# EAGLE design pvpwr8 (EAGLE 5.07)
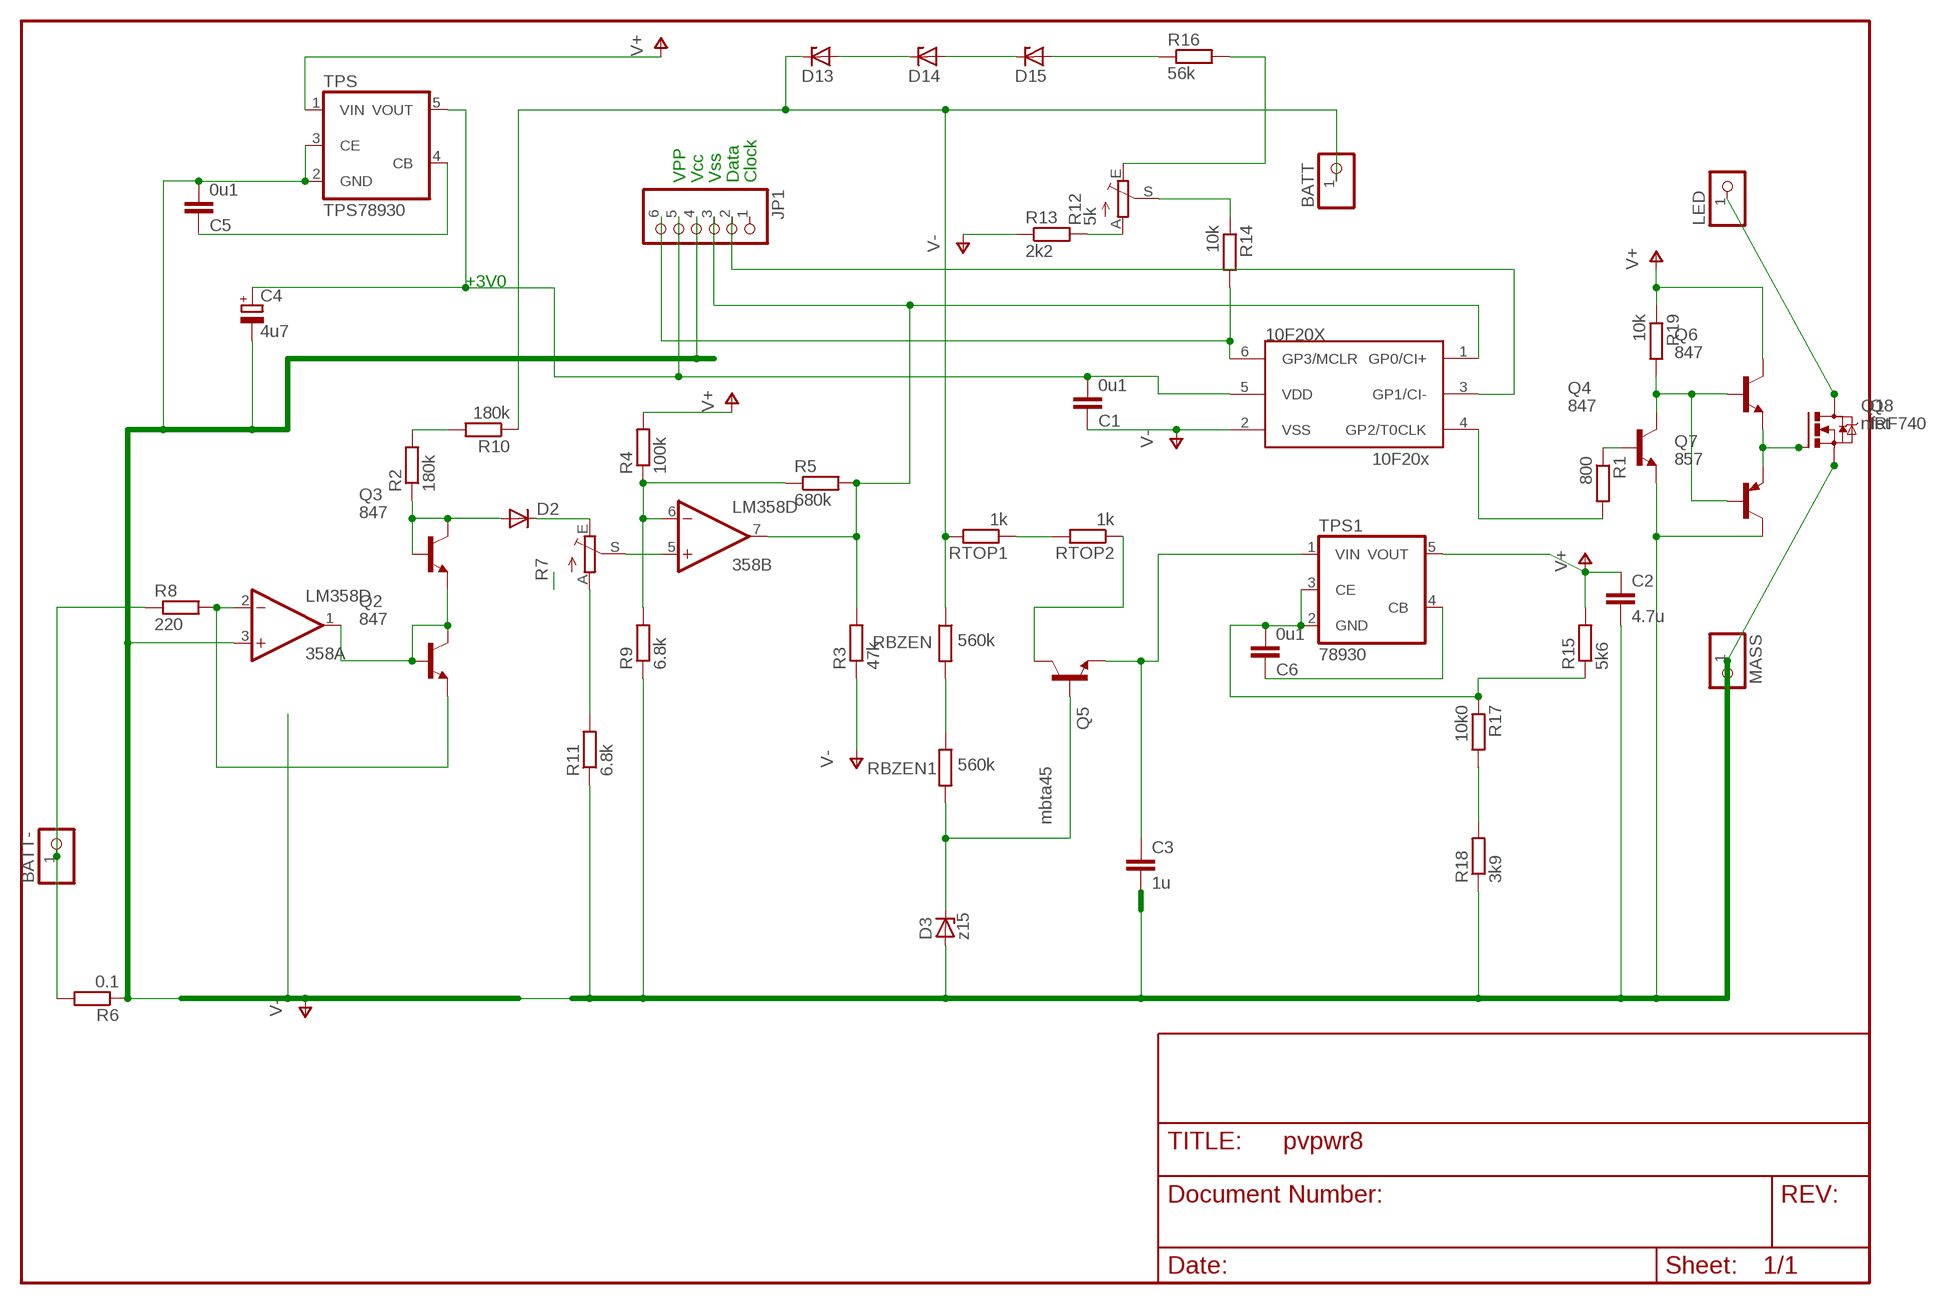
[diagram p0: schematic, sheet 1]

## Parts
10F20X  10F20x  PIC10F204OT  [SOT23-6]
358  LM358D  [SO08]
BATT  PINHD-1X1  [1X01]
BATT-  PINHD-1X1  [1X01]
C1  0u1  C-EUC1206  [C1206]
C2  4.7u  C-EUC1206  [C1206]
C3  1u  C-EUC1206  [C1206]
C4  4u7  CPOL-EUSMCA  [SMC_A]
C5  0u1  C-EUC0805  [C0805]
C6  0u1  C-EUC0805  [C0805]
D2  DIODE-SOD80C  [SOD80C]
D3  z15  ZENER-DIODESOD80C  [SOD80C]
D13  ZENER-DIODESOD80C  [SOD80C]
D14  ZENER-DIODESOD80C  [SOD80C]
D15  ZENER-DIODESOD80C  [SOD80C]
JP1  PINHD-1X6  [1X06BOX]
LED  PINHD-1X1  [1X01]
MASS  PINHD-1X1  [1X01]
Q1  nfet  N-HEXFET_DPAK-  [TO252]
Q2  847  BC847ALT1SMD  [SOT23]
Q3  847  BC847ALT1SMD  [SOT23]
Q4  847  BC847ALT1SMD  [SOT23]
Q5  mbta45  BC847ALT1SMD  [SOT23]
Q6  847  BC847ALT1SMD  [SOT23]
Q7  857  BC857ALT1SMD  [SOT23-BEC]
Q8  IRF740  [TO220BV]
R1  800  R-EU_R0805  [R0805]
R2  180k  R-EU_R1206  [R1206]
R3  47k  R-EU_R0805  [R0805]
R4  100k  R-EU_R0805  [R0805]
R5  680k  R-EU_R1206  [R1206]
R6  0.1  R-EU_R2512  [R2512]
R7  TRIM_EU-S64W  [S64W]
R8  220  R-EU_R0805  [R0805]
R9  6.8k  R-EU_R0805  [R0805]
R10  180k  R-EU_R1206  [R1206]
R11  6.8k  R-EU_R0805  [R0805]
R12  5k  TRIM_EU-S64W  [S64W]
R13  2k2  R-EU_R0805  [R0805]
R14  10k  R-EU_R0805  [R0805]
R15  5k6  R-EU_R0805  [R0805]
R16  56k  R-EU_R0805  [R0805]
R17  10k0  R-EU_R0805  [R0805]
R18  3k9  R-EU_R0805  [R0805]
R19  10k  R-EU_R0805  [R0805]
RBZEN  560k  R-EU_R1206  [R1206]
RBZEN1  560k  R-EU_R1206  [R1206]
RTOP1  1k  R-EU_R1206  [R1206]
RTOP2  1k  R-EU_R1206  [R1206]
TPS  TPS78930  TPS78930SOT23-5  [SOT25]
TPS1  78930  TPS78930SOT23-5  [SOT25]

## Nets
CB: D3.C Q5.1(B) RBZEN1.2
GND1: C6.1 TPS1.4(CB)
HOT: LED.1 Q1.3(D) Q8.D
N$1: Q4.1(B) R1.1
N$2: R7.A R11.2
N$3: BATT-.1 R6.2 R8.1
N$4: 10F20X.1(GP0/CI+) 358.7(B:OUT) JP1.3 R3.2 R5.2
N$5: 10F20X.4(GP2/T0CLK) R1.2
N$6: R2.2 R10.2
N$7: 358.1(A:OUT) Q2.1(B) Q2.3(C) Q3.2(E)
N$8: 10F20X.3(GP1/CI-) JP1.2
N$9: 10F20X.5(VDD) C1.2 C4.+ JP1.5 TPS.5(VOUT)
N$10: 358.2(A:-IN) Q2.2(E) R8.2
N$11: C5.1 TPS.4(CB)
N$12: D2.A Q3.1(B) Q3.3(C) R2.1
N$13: D2.C R7.E
N$15: 358.5(B:+IN) R7.S
N$16: Q5.3(C) RTOP2.1
N$17: 358.6(B:-IN) R4.1 R5.1 R9.2
N$18: D15.A R16.1
N$19: RBZEN1.1 RBZEN.2
N$21: Q4.3(C) Q6.1(B) Q7.B R19.2
N$23: D14.A D15.C
N$24: D13.A D14.C
N$25: R12.E R16.2
N$26: R12.A R13.2
N$27: R12.S R14.1
N$28: R17.2 R18.2
N$29: RTOP1.1 RTOP2.2
N$31: Q1.1(G) Q6.2(E) Q7.E Q8.G
PIR: 10F20X.6(GP3/MCLR) JP1.6 R14.2
V15: C3.1 Q5.2(E) TPS1.1(VIN)
V+: C2.1 Q6.3(C) R4.2 R15.2 R19.1 TPS1.5(VOUT) TPS.1(VIN)
V-: 10F20X.2(VSS) 358.3(A:+IN) C1.1 C2.2 C3.2 C4.- C5.2 D3.A JP1.4 MASS.1 Q1.2(S) Q4.2(E) Q7.C Q8.S R3.1 R6.1 R9.1 R11.1 R13.1 R18.1 TPS.2(GND) TPS.3(CE)
VPLUS: BATT.1 D13.C R10.1 RBZEN.1 RTOP1.2
X: C6.2 R15.1 R17.1 TPS1.2(GND) TPS1.3(CE)
Unconnected: JP1.1

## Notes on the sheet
- VPP | Vcc | Vss | Data | Clock
- +3V0

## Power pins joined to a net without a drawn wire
V+: 358.8(P:V+)
V-: 358.4(P:V-)

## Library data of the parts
10F20X = microchip-3:PIC10F2*: uPC nW 0,25/0,5k Program Flash memory Comparator
358 = linear:LM358: OP AMP also LM158; LM258; LM2904 Source: http://cache.national.com/ds/LM/LM158.pdf
BATT BATT- LED MASS = pinhead:PINHD-1X1: PIN HEADER
C1-C3 C5 C6 = rcl:C-EU: CAPACITOR, European symbol
C4 = rcl(2):CPOL-EU: POLARIZED CAPACITOR, European symbol
D2 = diode:DIODE-: DIODE
D3 D13-D15 = diode:ZENER-DIODE: Z-Diode
JP1 = pinhead:PINHD-1X6: PIN HEADER
Q1 = transistor-power:N-HEXFET_?-*: HEXFET® Power MOSFET
Q2-Q6 = transistor-npn:BC847*: NPN Transistor
Q7 = transistor-pnp:BC857*: PNP Transistror
Q8 = transistor-power:IRF740: N-CHANNEL MOS FET
R1-R6 R8-R11 R13-R19 RBZEN RBZEN1 RTOP1 RTOP2 = rcl:R-EU_: RESISTOR, European symbol
R7 R12 = pot:TRIM_EU-: POTENTIOMETER
TPS TPS1 = v-reg:TPS78930

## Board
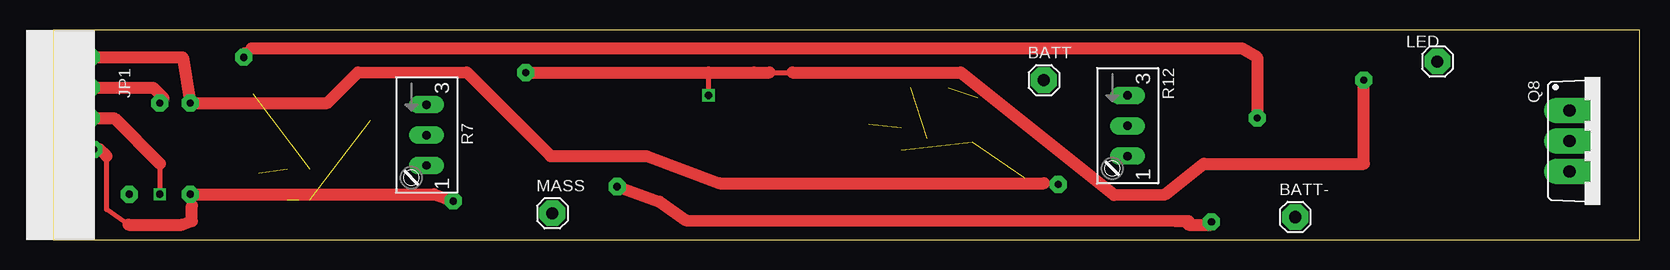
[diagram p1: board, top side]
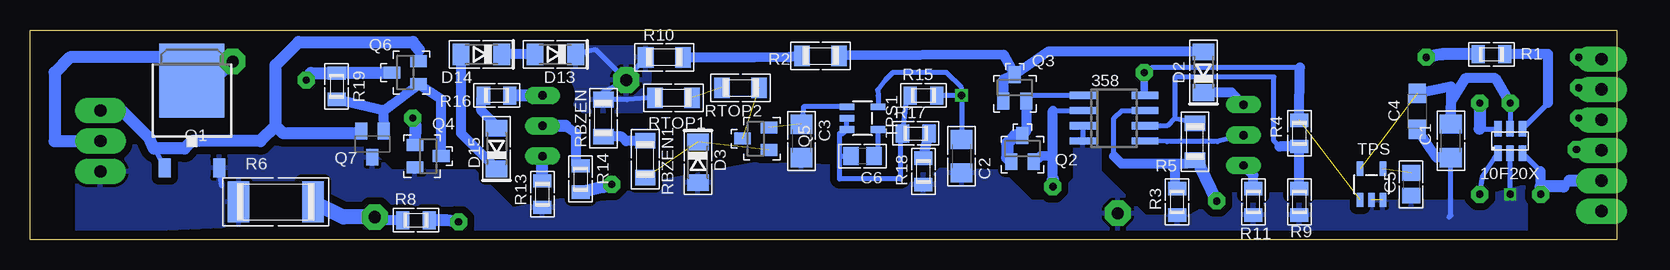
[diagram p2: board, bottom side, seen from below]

Size 132.24 x 17.5 mm. Coordinates in mm from the lower left corner, seen from the top.
Outline: 0,0 132.24,0 132.24,17.5 0,17.5 0,0
Copper layers (1*16): Top 0.035mm / dielectric 1.5mm / Bottom 0.035mm
Design rules "default *": minimum track width 10mil, minimum drill 24mil, track to track 8mil, track to pad 8mil, pad to pad 8mil, via to via 8mil, smd to smd 8mil, copper to edge 30mil, drill to drill 8mil, minimum pad ring 15mil, minimum via ring 8mil, stop-mask expansion 4mil, vias tented up to drill 0mil, thermal gap 10mil

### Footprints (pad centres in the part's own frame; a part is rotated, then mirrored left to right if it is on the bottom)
SOT23-6 = smd 0.635 x 1.27: 1 -1.016,-1.016; 2 0,-1.016; 3 1.016,-1.016; 4 1.016,1.016; 5 0,1.016; 6 -1.016,1.016
SO08 = smd 0.6 x 2.2: 1 -1.905,-2.6; 2 -0.635,-2.6; 3 0.635,-2.6; 4 1.905,-2.6; 5 1.905,2.6; 6 0.635,2.6; 7 -0.635,2.6; 8 -1.905,2.6
1X01 = drill 1.016 octagon: 1 0,0
C1206 = smd 1.6 x 1.8: 1 -1.4,0; 2 1.4,0
SMC_A = smd 1.6 x 1.4: + -1.5,0; - 1.5,0
C0805 = smd 1.3 x 1.5: 1 -0.95,0; 2 0.95,0
SOD80C = smd 1.4 x 1.8: A 1.7,0; C -1.7,0
1X06BOX = drill 1.016 long: 1 -6.35,0; 2 -3.81,0; 3 -1.27,0; 4 1.27,0; 5 3.81,0; 6 6.35,0
TO252 = smd 1 x 1.6: 1 -2.28,-3.53; 2 2.28,-3.53 | smd 5.4 x 6.2: 3 0,3.77
SOT23 = smd 1 x 1.4: 1 -0.95,-1.1; 2 0.95,-1.1; 3 0,1.1
SOT23-BEC = smd 1 x 1.4: B -0.95,-1.1; C 0,1.1; E 0.95,-1.1
TO220BV = drill 1.016 long: D 0,-2.54; G -2.54,-2.54; S 2.54,-2.54
R0805 = smd 1.1 x 1.5: 1 -1.1,0; 2 1.1,0
R1206 = smd 1.3 x 1.7: 1 -1.55,0; 2 1.55,0
R2512 = smd 1.8 x 3.4: 1 -3.1,0; 2 3.1,0
S64W = drill 0.7 long: A 2.54,1.27; E -2.54,1.27; S 0,1.27
SOT25 = smd 0.55 x 1.2: 1 -0.95,-1.3; 2 0,-1.3; 3 0.95,-1.3; 4 0.95,1.3; 5 -0.95,1.3

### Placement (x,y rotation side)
10F20X  8.89,8.26 0 bottom
358  41.91,10.16 270 bottom
BATT  82.55,13.34 0 top
BATT-  103.5,1.91 0 top
C1  13.84,8.26 90 bottom
C2  54.61,6.99 270 bottom
C3  67.94,8.26 270 bottom
C4  16.63,10.73 270 bottom
C5  17.14,4.63 270 bottom
C6  62.87,6.99 180 bottom
D2  34.45,14 90 bottom
D3  76.58,6.48 270 bottom
D13  88.46,15.5 180 bottom
D14  94.62,15.5 180 bottom
D15  93.34,7.62 90 bottom
JP1  1.27,8.75 90 top
LED  115.35,14.89 0 top
MASS  41.59,2.22 0 top
Q1  118.75,9.53 0 bottom
Q2  49.53,7.62 0 bottom
Q3  50.16,12.7 0 bottom
Q4  99.06,6.99 270 bottom
Q5  71.75,8.45 90 bottom
Q6  100.97,13.97 90 bottom
Q7  103.7,8 180 bottom
Q8  128.91,8.26 270 top
R1  10.45,15.5 0 bottom
R2  66.36,15.37 180 bottom
R3  36.64,3.17 90 bottom
R4  26.45,8.89 90 bottom
R5  35.15,8.2 270 bottom
R6  111.76,3.17 0 bottom
R7  29.84,8.75 270 top
R8  100.08,1.65 0 bottom
R9  26.45,3.17 90 bottom
R10  79.38,15.24 0 bottom
R11  30.29,3.17 90 bottom
R12  88.26,9.53 270 top
R13  89.53,3.81 90 bottom
R14  86.36,5.08 270 bottom
R15  57.79,12.06 0 bottom
R16  93.34,12.06 0 bottom
R17  58.42,8.89 0 bottom
R18  57.79,5.71 90 bottom
R19  106.68,12.83 270 bottom
RBZEN  84.46,10.16 270 bottom
RBZEN1  80.96,6.73 270 bottom
RTOP1  78.61,11.87 180 bottom
RTOP2  73.03,12.7 180 bottom
TPS  20.45,4.63 0 bottom
TPS1  62.87,10.16 270 bottom

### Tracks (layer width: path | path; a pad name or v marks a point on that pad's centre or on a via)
CB  (2 unrouted)
GND1
  Bottom 0.406: C6.1 61.56,7.62 TPS1.4
HOT
  Bottom 1.016: LED.1 116.94,13.29 Q1.3 119.38,13.29 121.32,15.24 128.91,15.24 130.18,13.97 130.18,8.26 Q8.D
N$1  (via drill 0.6 pad 1.42)
  Top 0.406: v15.88,15.24 15.88,15.88 16.51,16
  Top 1.016: 16.51,16 99.06,16 100.33,15.24 v100.33,10.16
  Bottom 0.406: v100.33,10.16 100.14,9.69
  Bottom 1.016: R1.1 14.53,15.49 v15.88,15.24 | 100.14,9.69 Q4.1
N$2
  Bottom 0.813: R11.2 30.29,5.38 R7.A
N$3
  Bottom 0.406: 103.25,1.65 BATT-.1
  Bottom 0.813: R8.1 103.25,1.65
  Bottom 1.27: BATT-.1 106.12,1.91 R6.2
N$4  (via drill 0.6 pad 1.42)
  Top 0.406: 4.45,6.99 4.45,2.54 6.29,1.27 | 11.56,2.86 v11.43,3.81
  Top 1.016: v33.34,3.24 31.75,3.81 v11.43,3.81 | 6.29,1.27 10.73,1.27 11.56,1.59 11.56,2.86 | v3.37,7.56 3.87,7.56 4.45,6.99
  Bottom 0.406: 10F20X.1 11.18,5.33 v11.43,3.81 | 358.7 41.27,10.79 41.91,10.16 41.91,6.99 | 36.83,4.85 R3.2 | R5.2 34.7,6.13 35.88,6.35
  Bottom 0.813: 41.91,6.99 41.27,6.35 36.83,6.35 | 35.88,6.35 36.83,6.35 | 36.83,6.35 36.83,4.85
  Bottom 1.016: v33.34,3.24 34.7,6.13 | JP1.3 3.29,7.48 v3.37,7.56
N$5
  Bottom 0.406: 10F20X.4 5.71,11.43
  Bottom 0.813: 5.71,11.43 5.71,15.51 R1.2
N$6
  Bottom 0.406: 77.32,15.23 R10.2
  Bottom 0.813: R2.2 69.02,15.24 71.88,15.23 77.32,15.23
N$7
  Bottom 0.406: 358.1 48.75,12.06 Q3.2 | 49.22,9.04 Q2.3
  Bottom 0.813: Q3.2 49.22,9.04
  Bottom 1.016: Q2.3 50.15,8.72 50.8,8.06 50.8,6.84 Q2.1
N$8  (via drill 0.6 pad 1.42)
  Bottom 0.406: 6.35,4.45 v6.35,3.81 | 6.35,5.71 10F20X.3 | 3.95,4.94 4.45,4.45
  Bottom 0.813: 6.35,4.45 6.35,5.71
  Bottom 1.016: JP1.2 3.95,4.94 | 4.45,4.45 6.35,4.45
N$9  (via drill 0.6 pad 1.42)  (1 unrouted)
  Top 0.406: 9.2,11.83 9.2,11.74 v8.89,11.43
  Top 1.016: v3.18,12.7 8.33,12.7 9.2,11.83
  Bottom 0.406: v8.89,11.43 10F20X.5
  Bottom 0.813: C4.+ 13.8,12.8 C1.2 13.84,11.56 12.64,13.5 10.1,13.5 v8.89,11.43
  Bottom 1.016: JP1.5 3.04,12.56 v3.18,12.7
N$10  (via drill 0.6 pad 1.42)
  Top 0.406: 94.62,1.59 94.62,1.27 | 96.52,1.27 v96.52,1.5
  Top 1.016: 94.62,1.59 93.54,1.59 52.7,1.64 50.55,3.17 v46.99,4.45 | 94.62,1.27 96.52,1.27
  Bottom 0.406: 46.99,10.79 358.2
  Bottom 0.813: 46.99,6.99 46.99,10.79 | 46.99,5.08 46.99,6.99 | Q2.2 48.01,6.98 46.99,6.99
  Bottom 1.016: R8.2 97.54,1.65 v96.52,1.5 | v46.99,4.45 46.99,5.08
N$11  (1 unrouted)
N$12
  Bottom 0.406: 47.28,15.7 47.33,15.75
  Bottom 0.813: 47.33,15.75 Q3.3 | Q3.1 51.12,13.42 Q3.3 | R2.1 51.08,15.44 Q3.3 | D2.A 47.28,15.7
N$13
  Bottom 0.406: R7.E 31.9,12.08
  Bottom 0.813: D2.C 32.12,12.3 R7.E
N$15
  Bottom 0.406: R7.S 33.29,8.2 37.47,8.2 358.5
N$16  (1 unrouted)
N$17
  Bottom 0.406: 358.6 37.47,9.53 36.83,10.16 | 36.83,10.16 35.9,9.97 R5.1 | 28.11,7.79 28.57,8.26 28.57,13.6 36.83,13.6 36.83,10.16
  Bottom 0.813: 28.11,7.79 R4.1 R9.2
N$18
  Bottom 0.406: D15.A 93.34,9.53 | 94.62,11.89 R16.1
  Bottom 0.813: 93.34,9.53 94.62,10.79 94.62,11.89
N$19
  Bottom 0.406: RBZEN1.1 81.63,8.26
  Bottom 0.813: RBZEN.2 82.91,8.61 82.55,8.26 81.63,8.26
N$21
  Bottom 0.406: Q7.B 102.75,10.78 | Q6.1 100.19,12.7
  Bottom 0.813: Q4.3 97.96,11.75 Q6.1 | 102.75,10.78 R19.2 | Q7.B 102.81,10.73 102.04,11.3 100.19,12.7
N$23
  Bottom 0.813: D14.A 96.31,8.89 D15.C
N$24
  Bottom 0.406: D13.A 90.81,15.5
  Bottom 0.813: 90.81,15.5 D14.C
N$25
  Bottom 1.016: R12.E R16.2
N$26
  Bottom 1.016: R13.2 R12.A
N$27
  Bottom 0.406: R14.1 86.69,6.18
  Bottom 0.813: 87.63,9.53 86.69,8.89 86.69,6.18
  Bottom 1.016: 87.63,9.53 R12.S
N$28
  Bottom 0.813: R18.2 R17.2
N$29  (1 unrouted)
N$31
  Bottom 0.406: 99.82,15.87 Q6.2 | Q7.E 105.26,8.89 | 122.29,8.52 Q1.1
  Bottom 1.016: 99.82,15.87 100.33,16.51 109.85,16.51 111.76,14.61 111.76,9.53 | 111.76,9.53 111.12,8.89 105.26,8.89 | 111.76,9.53 113.03,8.26 118.75,8.26 119.38,7.62 121.92,7.62 122.29,8.52 124.57,10.79 Q8.G
PIR  (via drill 0.6 pad 1.42)
  Top 0.406: 82.55,4.71 v83.76,4.64
  Top 1.016: 82.55,4.71 55.54,4.71 49.45,7 41.45,7 34.45,14 25.4,13.97 22.86,11.43 v11.43,11.43 10.79,15.24 v3.18,15.24
  Bottom 0.406: 11.43,9.27 10F20X.6 | v83.76,4.64 84.46,4.4
  Bottom 1.016: 84.46,4.4 R14.2 | v11.43,11.43 11.43,9.27 | JP1.6 3.04,15.1 v3.18,15.24
V15  (1 unrouted)
  Bottom 0.406: TPS1.1 67.76,11.11 C3.1
V+  (via drill 0.6, 0.6 pad 1.42)  (1 unrouted)
  Top 0.406: 54.61,13.97 v54.61,12.06 | 58.42,13.97 61.59,13.97
  Top 1.016: v109.22,13.34 109.22,6.35 95.88,6.35 92.71,3.81 88.39,3.75 75.63,13.97 61.59,13.97 | v39.37,13.97 54.61,13.97 58.42,13.97 59.69,13.97
  Bottom 0.406: R19.1 105.81,13.97 | 26.42,14.4 38.73,14.4 v39.37,13.97 | 39.37,12.12 358.8 | v54.61,12.06 C2.1 | v54.61,12.06 54.61,12.7 55.88,13.97 60.33,13.97 60.96,13.34 61.59,12.51 61.56,12.04 TPS1.5 | v54.61,12.06 R15.2
  Bottom 0.61: v39.37,13.97 39.37,12.12
  Bottom 0.813: R4.2 26.42,14.4
  Bottom 1.016: R19.1 108.82,13.93 v109.22,13.34 | 105.81,13.97 Q6.3
V-  (via drill 0.6, 0.6 pad 1.42)  (1 unrouted)
  Top 0.406: 8.89,6.35 v8.89,3.81
  Top 1.016: v3.18,10.16 5.08,10.16 8.89,6.35
  Bottom 0.406: 116.26,4.52 Q1.2 | v8.89,3.81 10F20X.2 | C1.1 13.84,2.04 13.97,1.91 | 358.3 358.4
  Bottom 0.813: C1.1 15.03,6.86 C4.-
  Bottom 1.016: JP1.4 3.04,10.02 v3.18,10.16
  pour Bottom (isolate 0.61): 7.62,4.45 7.62,0.64 95.88,0.64 97.16,1.91 105.41,1.91 108.59,5.08 114.3,5.08 114.3,1.27 128.27,0.64 128.27,6.99 119.38,8.89 105.41,8.89 102.24,5.71 95.25,5.71 92.07,2.54 71.75,6.35 51.44,5.71 48.9,3.17 46.99,3.17 45.09,5.08 45.09,8.26 45.72,8.89 44.45,8.89 43.18,7.62 43.18,5.71 39.37,1.91 35.56,1.91 32.39,3.81 26.67,3.81 26.67,3.17 10.79,3.17 10.16,3.81
VPLUS
  Bottom 0.406: D13.C 85.09,15.88 BATT.1 | BATT.1 84.46,12.35 RBZEN.1 82.47,11.71 RTOP1.2 | BATT.1 R10.1
  pour Bottom (isolate 1.27): 80.65,17.14 86.36,17.14 87,15.88 87,11.43 86.36,10.79 81.28,10.79 80.65,11.43
X
  Bottom 0.406: R15.1 59.23,11.43 R17.1 59.69,8.89 59.69,5.08 64.77,5.08 64.77,6.99 | 64.77,6.99 64.77,8.89 64.48,8.89 TPS1.3 TPS1.2 | 64.77,6.99 C6.2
